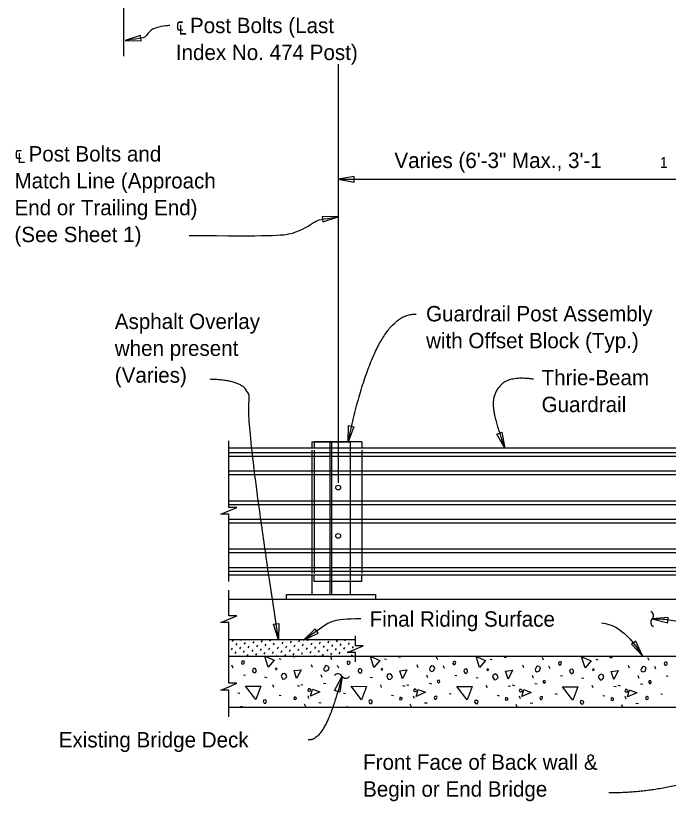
# Model space of a CAD drawing. Extents: x 21652.5 to 21723.2, y 56079.2 to 56117.9.
# Drawn here: x 21654.45 to 21663, y 56092.54 to 56102.84 of the extents above; entities that cross this region are included whole.
import ezdxf

# ---------------------------------------------------------------- set-up
doc = ezdxf.new("R2010")
doc.units = 0
for name, color, linetype in [('Dimension', 7, 'Continuous'), ('ExistSuperStruct', 7, 'Continuous'), ('Miscellaneous', 7, 'Continuous'), ('SteelMisc', 7, 'Continuous'), ('SteelMisc_h', 7, 'Continuous'), ('TextStructures', 7, 'Continuous')]:
    doc.layers.add(name, color=color, linetype=linetype)

msp = doc.modelspace()

# ---------------------------------------------------------------- linework, layer by layer
at = {"layer": 'Dimension'}
for p, q in [((21655.863, 56102.304), (21655.863, 56106.913)), ((21658.671, 56102.202), (21658.671, 56096.715))]:
    msp.add_line(p, q, dxfattribs=at)
for points in [[(21655.88, 56102.511), (21656.091, 56102.505), (21656.081, 56102.575)], [(21658.671, 56100.692), (21658.879, 56100.656), (21658.879, 56100.727)], [(21658.671, 56100.2), (21658.46, 56100.206), (21658.47, 56100.136)], [(21658.803, 56097.253), (21658.808, 56097.465), (21658.877, 56097.451)], [(21660.854, 56097.171), (21660.749, 56097.354), (21660.815, 56097.378)], [(21657.89, 56094.661), (21657.825, 56094.862), (21657.895, 56094.872)], [(21662.783, 56094.932), (21662.988, 56094.882), (21662.993, 56094.952)], [(21658.218, 56094.654), (21658.409, 56094.745), (21658.368, 56094.803)], [(21662.658, 56094.448), (21662.571, 56094.641), (21662.513, 56094.602)], [(21658.722, 56094.184), (21658.691, 56093.975), (21658.624, 56093.996)]]:
    msp.add_lwpolyline(points, close=True, dxfattribs=at)
for points in [[(21658.671, 56100.692), (21672.529, 56100.692)], [(21657.239, 56095.421), (21657.239, 56096.304), (21657.135, 56096.304), (21657.239, 56096.349), (21657.342, 56096.394), (21657.239, 56096.394), (21657.239, 56097.267)], [(21657.239, 56094.414), (21657.239, 56094.884), (21657.135, 56094.884), (21657.239, 56094.929), (21657.342, 56094.974), (21657.239, 56094.974), (21657.239, 56095.308)], [(21658.897, 56094.37), (21658.897, 56094.491), (21658.793, 56094.491), (21658.897, 56094.536), (21659, 56094.581), (21658.897, 56094.581), (21658.897, 56094.711)], [(21657.239, 56093.649), (21657.239, 56093.999), (21657.135, 56093.999), (21657.239, 56094.044), (21657.342, 56094.089), (21657.239, 56094.089), (21657.239, 56094.414)]]:
    msp.add_lwpolyline(points, dxfattribs=at)
for centre, start, end in [((21662.742, 56094.974), 314.1793, 65.9065), ((21662.825, 56094.889), 134.1793, 245.9065), ((21658.669, 56094.154), 30.0081, 141.7354), ((21658.772, 56094.214), 210.0081, 321.7354)]:
    msp.add_arc(centre, 0.0596, start, end, dxfattribs=at)
for points, degree in [([(21656.465, 56102.707), (21656.444, 56102.705), (21656.22, 56102.689), (21656.148, 56102.543), (21656.114, 56102.544), (21655.88, 56102.511)], 3), ([(21656.717, 56099.956), (21657.781, 56099.95), (21658.1, 56099.953), (21658.403, 56100.168), (21658.437, 56100.167), (21658.671, 56100.2)], 3), ([(21658.803, 56097.254), (21659.157, 56098.955), (21659.693, 56098.924)], 2), ([(21657.891, 56094.66), (21657.457, 56097.477), (21657.55, 56098.065), (21656.988, 56098.072)], 2), ([(21661.23, 56098.074), (21660.931, 56098.115), (21660.699, 56097.903), (21660.704, 56097.578), (21660.854, 56097.171)], 2), ([(21658.967, 56094.934), (21658.773, 56094.932), (21658.585, 56094.912), (21658.513, 56094.862), (21658.218, 56094.654)], 3), ([(21662.121, 56094.88), (21662.263, 56094.866), (21662.44, 56094.736), (21662.537, 56094.628), (21662.658, 56094.448)], 3), ([(21665.308, 56093.168), (21664.014, 56094.932), (21662.783, 56094.932)], 2), ([(21658.722, 56094.184), (21658.501, 56093.31), (21658.278, 56093.35)], 2), ([(21663.545, 56092.873), (21662.881, 56092.653), (21662.218, 56092.653)], 2)]:
    msp.add_open_spline(points, degree=degree, dxfattribs=at)
at = {"layer": 'ExistSuperStruct'}
for p, q in [((21657.239, 56095.192), (21663.412, 56095.192)), ((21658.897, 56094.66), (21657.239, 56094.66)), ((21663.412, 56094.442), (21657.239, 56094.442)), ((21657.239, 56093.775), (21663.412, 56093.775))]:
    msp.add_line(p, q, dxfattribs=at)
at = {"layer": 'Miscellaneous'}
for p, q in [((21658.983, 56097.254), (21658.358, 56097.254)), ((21658.358, 56097.254), (21658.358, 56097.171)), ((21658.983, 56097.254), (21658.983, 56097.171)), ((21658.358, 56097.142), (21658.358, 56095.53)), ((21658.983, 56097.142), (21658.983, 56095.53)), ((21658.358, 56095.421), (21658.358, 56095.504)), ((21658.983, 56095.421), (21658.983, 56095.504)), ((21658.983, 56095.421), (21658.358, 56095.421)), ((21657.286, 56094.638), (21657.298, 56094.66)), ((21657.334, 56094.589), (21657.347, 56094.612)), ((21657.383, 56094.54), (21657.396, 56094.563)), ((21657.396, 56094.651), (21657.402, 56094.66)), ((21657.445, 56094.602), (21657.458, 56094.625)), ((21657.494, 56094.553), (21657.507, 56094.576)), ((21657.556, 56094.615), (21657.569, 56094.637)), ((21657.604, 56094.566), (21657.617, 56094.589)), ((21657.666, 56094.628), (21657.679, 56094.65)), ((21657.715, 56094.579), (21657.728, 56094.602)), ((21657.777, 56094.641), (21657.788, 56094.66)), ((21657.826, 56094.592), (21657.839, 56094.615)), ((21657.875, 56094.543), (21657.888, 56094.566)), ((21657.888, 56094.654), (21657.891, 56094.66)), ((21657.936, 56094.605), (21657.949, 56094.628)), ((21657.985, 56094.556), (21657.998, 56094.579)), ((21658.047, 56094.618), (21658.06, 56094.641)), ((21658.096, 56094.569), (21658.109, 56094.592)), ((21658.158, 56094.631), (21658.171, 56094.653)), ((21658.206, 56094.582), (21658.219, 56094.605)), ((21658.268, 56094.644), (21658.278, 56094.66)), ((21658.317, 56094.595), (21658.33, 56094.618)), ((21658.366, 56094.546), (21658.379, 56094.569)), ((21658.379, 56094.657), (21658.381, 56094.66)), ((21658.428, 56094.608), (21658.441, 56094.631)), ((21658.477, 56094.559), (21658.49, 56094.582)), ((21658.538, 56094.621), (21658.551, 56094.644)), ((21658.587, 56094.572), (21658.6, 56094.595)), ((21658.649, 56094.634), (21658.662, 56094.656)), ((21658.698, 56094.585), (21658.711, 56094.608)), ((21658.76, 56094.647), (21658.767, 56094.66)), ((21658.808, 56094.598), (21658.821, 56094.621)), ((21658.857, 56094.549), (21658.87, 56094.572)), ((21658.87, 56094.66), (21658.871, 56094.66)), ((21657.273, 56094.527), (21657.286, 56094.55)), ((21657.321, 56094.479), (21657.334, 56094.501)), ((21657.432, 56094.491), (21657.445, 56094.514)), ((21657.481, 56094.443), (21657.494, 56094.465)), ((21657.543, 56094.504), (21657.556, 56094.527)), ((21657.592, 56094.456), (21657.604, 56094.478)), ((21657.653, 56094.517), (21657.666, 56094.54)), ((21657.702, 56094.469), (21657.715, 56094.491)), ((21657.764, 56094.53), (21657.777, 56094.553)), ((21657.813, 56094.482), (21657.826, 56094.504)), ((21657.923, 56094.495), (21657.936, 56094.517)), ((21657.972, 56094.446), (21657.985, 56094.468)), ((21658.034, 56094.507), (21658.047, 56094.53)), ((21658.083, 56094.459), (21658.096, 56094.481)), ((21658.145, 56094.52), (21658.158, 56094.543)), ((21658.194, 56094.472), (21658.206, 56094.494)), ((21658.255, 56094.533), (21658.268, 56094.556)), ((21658.304, 56094.485), (21658.317, 56094.507)), ((21658.356, 56094.442), (21658.366, 56094.458)), ((21658.415, 56094.498), (21658.428, 56094.52)), ((21658.464, 56094.449), (21658.477, 56094.471)), ((21658.525, 56094.511), (21658.538, 56094.533)), ((21658.574, 56094.462), (21658.587, 56094.484)), ((21658.636, 56094.523), (21658.649, 56094.546)), ((21658.685, 56094.475), (21658.698, 56094.497)), ((21658.747, 56094.536), (21658.76, 56094.559)), ((21658.796, 56094.488), (21658.808, 56094.51)), ((21658.846, 56094.442), (21658.857, 56094.461)), ((21658.906, 56094.501), (21658.906, 56094.501)), ((21657.377, 56094.442), (21657.383, 56094.452)), ((21657.764, 56094.442), (21657.764, 56094.442)), ((21657.867, 56094.442), (21657.875, 56094.455)), ((21657.892, 56094.414), (21657.92, 56094.407)), ((21658.253, 56094.442), (21658.255, 56094.445)), ((21658.59, 56094.398), (21658.576, 56094.434)), ((21658.743, 56094.442), (21658.747, 56094.448)), ((21659.277, 56094.411), (21659.305, 56094.404)), ((21659.975, 56094.395), (21659.961, 56094.43)), ((21660.662, 56094.407), (21660.69, 56094.4)), ((21661.36, 56094.391), (21661.346, 56094.427)), ((21662.046, 56094.404), (21662.075, 56094.397)), ((21662.745, 56094.388), (21662.73, 56094.423)), ((21657.294, 56094.289), (21657.279, 56094.325)), ((21658.334, 56094.298), (21658.32, 56094.333)), ((21658.678, 56094.286), (21658.664, 56094.321)), ((21659.719, 56094.294), (21659.705, 56094.33)), ((21660.063, 56094.282), (21660.049, 56094.318)), ((21661.104, 56094.291), (21661.089, 56094.326)), ((21661.448, 56094.279), (21661.433, 56094.314)), ((21662.488, 56094.287), (21662.474, 56094.322)), ((21662.832, 56094.275), (21662.818, 56094.311)), ((21657.431, 56094.201), (21657.456, 56094.198)), ((21657.707, 56094.173), (21657.737, 56094.167)), ((21658.46, 56094.165), (21658.447, 56094.199)), ((21659.092, 56094.169), (21659.122, 56094.164)), ((21659.844, 56094.162), (21659.832, 56094.195)), ((21660.201, 56094.194), (21660.226, 56094.19)), ((21660.477, 56094.166), (21660.507, 56094.16)), ((21661.229, 56094.158), (21661.217, 56094.192)), ((21661.585, 56094.19), (21661.61, 56094.187)), ((21661.861, 56094.162), (21661.891, 56094.157)), ((21662.614, 56094.154), (21662.601, 56094.188)), ((21662.97, 56094.187), (21662.995, 56094.183)), ((21657.829, 56094.035), (21657.816, 56094.069)), ((21658.135, 56094.061), (21658.163, 56094.054)), ((21658.182, 56094.075), (21658.21, 56094.068)), ((21658.478, 56094.093), (21658.509, 56094.088)), ((21659.24, 56094.035), (21659.228, 56094.069)), ((21659.514, 56094.061), (21659.543, 56094.054)), ((21659.567, 56094.071), (21659.595, 56094.064)), ((21659.863, 56094.09), (21659.893, 56094.084)), ((21660.625, 56094.031), (21660.613, 56094.065)), ((21660.899, 56094.058), (21660.927, 56094.051)), ((21660.951, 56094.068), (21660.98, 56094.061)), ((21661.248, 56094.086), (21661.278, 56094.081)), ((21662.01, 56094.028), (21661.997, 56094.061)), ((21662.284, 56094.054), (21662.312, 56094.047)), ((21662.336, 56094.064), (21662.364, 56094.057)), ((21662.633, 56094.083), (21662.663, 56094.077)), ((21657.357, 56093.964), (21657.384, 56093.959)), ((21658.742, 56093.961), (21658.768, 56093.955)), ((21660.127, 56093.957), (21660.153, 56093.952)), ((21661.511, 56093.954), (21661.538, 56093.948)), ((21662.896, 56093.95), (21662.922, 56093.945)), ((21657.897, 56093.936), (21657.924, 56093.931)), ((21658.288, 56093.892), (21658.276, 56093.926)), ((21659.368, 56093.936), (21659.394, 56093.931)), ((21659.673, 56093.889), (21659.66, 56093.922)), ((21660.752, 56093.932), (21660.779, 56093.927)), ((21661.058, 56093.885), (21661.045, 56093.919)), ((21662.137, 56093.929), (21662.164, 56093.924)), ((21662.442, 56093.882), (21662.43, 56093.915)), ((21658.246, 56093.783), (21658.232, 56093.818)), ((21658.418, 56093.839), (21658.45, 56093.835)), ((21659.63, 56093.779), (21659.616, 56093.815)), ((21659.803, 56093.835), (21659.835, 56093.832)), ((21661.015, 56093.776), (21661.001, 56093.811)), ((21661.188, 56093.832), (21661.22, 56093.828)), ((21662.399, 56093.775), (21662.386, 56093.807)), ((21662.572, 56093.828), (21662.604, 56093.825))]:
    msp.add_line(p, q, dxfattribs=at)
for points in [[(21657.403, 56094.357), (21657.412, 56094.341), (21657.431, 56094.343), (21657.44, 56094.355), (21657.442, 56094.374), (21657.43, 56094.38), (21657.421, 56094.381), (21657.41, 56094.378), (21657.407, 56094.374), (21657.403, 56094.357)], [(21657.755, 56094.302), (21657.71, 56094.442)], [(21657.723, 56094.442), (21657.833, 56094.394), (21657.755, 56094.302)], [(21658.079, 56094.442), (21658.08, 56094.439), (21658.077, 56094.442)], [(21658.08, 56094.439), (21658.101, 56094.439), (21658.103, 56094.442)], [(21658.788, 56094.353), (21658.797, 56094.337), (21658.816, 56094.339), (21658.825, 56094.351), (21658.827, 56094.371), (21658.814, 56094.376), (21658.806, 56094.378), (21658.795, 56094.374), (21658.791, 56094.371), (21658.788, 56094.353)], [(21659.14, 56094.298), (21659.093, 56094.442)], [(21659.1, 56094.442), (21659.217, 56094.39), (21659.14, 56094.298)], [(21659.462, 56094.442), (21659.464, 56094.436), (21659.461, 56094.439)], [(21659.464, 56094.436), (21659.485, 56094.436), (21659.491, 56094.442)], [(21660.173, 56094.35), (21660.181, 56094.334), (21660.201, 56094.335), (21660.21, 56094.348), (21660.211, 56094.367), (21660.199, 56094.373), (21660.19, 56094.374), (21660.18, 56094.371), (21660.176, 56094.367), (21660.173, 56094.35)], [(21660.524, 56094.295), (21660.477, 56094.442), (21660.602, 56094.387), (21660.524, 56094.295)], [(21660.845, 56094.442), (21660.849, 56094.432), (21660.845, 56094.436)], [(21660.849, 56094.432), (21660.87, 56094.432), (21660.88, 56094.442)], [(21661.557, 56094.346), (21661.566, 56094.33), (21661.585, 56094.332), (21661.594, 56094.344), (21661.596, 56094.364), (21661.584, 56094.369), (21661.575, 56094.371), (21661.564, 56094.367), (21661.561, 56094.364), (21661.557, 56094.346)], [(21661.909, 56094.291), (21661.861, 56094.438), (21661.987, 56094.383), (21661.909, 56094.291)], [(21662.229, 56094.442), (21662.228, 56094.441), (21662.234, 56094.429), (21662.23, 56094.432)], [(21662.234, 56094.429), (21662.255, 56094.429), (21662.265, 56094.439), (21662.265, 56094.442)], [(21662.942, 56094.343), (21662.951, 56094.327), (21662.97, 56094.328), (21662.979, 56094.341), (21662.981, 56094.36), (21662.968, 56094.365), (21662.96, 56094.367), (21662.949, 56094.364), (21662.945, 56094.36), (21662.942, 56094.343)], [(21657.548, 56094.258), (21657.559, 56094.236), (21657.576, 56094.226), (21657.591, 56094.236), (21657.598, 56094.247), (21657.598, 56094.268), (21657.582, 56094.284), (21657.562, 56094.282), (21657.553, 56094.274), (21657.548, 56094.258)], [(21657.854, 56094.266), (21657.873, 56094.275), (21657.866, 56094.282), (21657.854, 56094.288), (21657.849, 56094.275), (21657.854, 56094.266)], [(21658.127, 56094.151), (21658.094, 56094.255), (21658.187, 56094.268), (21658.127, 56094.151)], [(21658.488, 56094.261), (21658.511, 56094.248), (21658.541, 56094.261), (21658.553, 56094.298), (21658.536, 56094.315), (21658.513, 56094.321), (21658.502, 56094.314), (21658.49, 56094.294), (21658.481, 56094.278), (21658.488, 56094.261)], [(21658.933, 56094.254), (21658.943, 56094.233), (21658.961, 56094.222), (21658.975, 56094.233), (21658.982, 56094.244), (21658.982, 56094.265), (21658.966, 56094.281), (21658.947, 56094.279), (21658.938, 56094.27), (21658.933, 56094.254)], [(21659.239, 56094.263), (21659.258, 56094.272), (21659.251, 56094.279), (21659.239, 56094.284), (21659.233, 56094.272), (21659.239, 56094.263)], [(21659.512, 56094.147), (21659.478, 56094.252), (21659.572, 56094.264), (21659.512, 56094.147)], [(21659.873, 56094.257), (21659.896, 56094.245), (21659.926, 56094.257), (21659.938, 56094.294), (21659.92, 56094.312), (21659.897, 56094.317), (21659.887, 56094.31), (21659.874, 56094.291), (21659.866, 56094.275), (21659.873, 56094.257)], [(21660.317, 56094.251), (21660.328, 56094.229), (21660.346, 56094.219), (21660.36, 56094.229), (21660.367, 56094.24), (21660.367, 56094.261), (21660.351, 56094.277), (21660.332, 56094.275), (21660.323, 56094.266), (21660.317, 56094.251)], [(21660.623, 56094.259), (21660.643, 56094.268), (21660.636, 56094.275), (21660.623, 56094.281), (21660.618, 56094.268), (21660.623, 56094.259)], [(21660.897, 56094.144), (21660.863, 56094.248), (21660.957, 56094.261), (21660.897, 56094.144)], [(21661.257, 56094.253), (21661.28, 56094.241), (21661.31, 56094.253), (21661.323, 56094.291), (21661.305, 56094.308), (21661.282, 56094.314), (21661.271, 56094.307), (21661.259, 56094.287), (21661.25, 56094.271), (21661.257, 56094.253)], [(21661.702, 56094.247), (21661.713, 56094.226), (21661.73, 56094.215), (21661.745, 56094.226), (21661.752, 56094.236), (21661.752, 56094.258), (21661.736, 56094.274), (21661.716, 56094.272), (21661.707, 56094.263), (21661.702, 56094.247)], [(21662.008, 56094.256), (21662.027, 56094.265), (21662.02, 56094.272), (21662.008, 56094.277), (21662.003, 56094.265), (21662.008, 56094.256)], [(21662.281, 56094.14), (21662.248, 56094.245), (21662.341, 56094.257), (21662.281, 56094.14)], [(21662.642, 56094.25), (21662.665, 56094.238), (21662.695, 56094.25), (21662.707, 56094.287), (21662.69, 56094.305), (21662.667, 56094.31), (21662.656, 56094.303), (21662.644, 56094.284), (21662.635, 56094.268), (21662.642, 56094.25)], [(21657.925, 56094.182), (21657.948, 56094.145), (21657.971, 56094.146), (21657.979, 56094.155), (21657.999, 56094.175), (21657.987, 56094.205), (21657.962, 56094.219), (21657.944, 56094.212), (21657.93, 56094.198), (21657.925, 56094.182)], [(21659.309, 56094.178), (21659.332, 56094.141), (21659.355, 56094.143), (21659.364, 56094.152), (21659.384, 56094.171), (21659.371, 56094.201), (21659.346, 56094.215), (21659.329, 56094.208), (21659.315, 56094.194), (21659.309, 56094.178)], [(21660.694, 56094.175), (21660.717, 56094.137), (21660.74, 56094.139), (21660.749, 56094.148), (21660.768, 56094.167), (21660.756, 56094.198), (21660.731, 56094.212), (21660.713, 56094.205), (21660.699, 56094.19), (21660.694, 56094.175)], [(21662.079, 56094.171), (21662.102, 56094.134), (21662.125, 56094.136), (21662.133, 56094.145), (21662.153, 56094.164), (21662.141, 56094.194), (21662.116, 56094.208), (21662.098, 56094.201), (21662.084, 56094.187), (21662.079, 56094.171)], [(21657.592, 56093.878), (21657.458, 56094.054), (21657.658, 56094.053), (21657.592, 56093.878)], [(21658.977, 56093.874), (21658.843, 56094.051), (21659.042, 56094.049), (21658.977, 56093.874)], [(21659.975, 56094.102), (21659.985, 56094.091), (21659.996, 56094.099), (21660.003, 56094.109), (21659.999, 56094.127), (21659.99, 56094.129), (21659.978, 56094.127), (21659.967, 56094.116), (21659.975, 56094.102)], [(21660.362, 56093.871), (21660.227, 56094.047), (21660.427, 56094.046), (21660.362, 56093.871)], [(21661.359, 56094.099), (21661.37, 56094.088), (21661.38, 56094.095), (21661.387, 56094.106), (21661.384, 56094.123), (21661.375, 56094.125), (21661.363, 56094.123), (21661.352, 56094.113), (21661.359, 56094.099)], [(21662.744, 56094.095), (21662.754, 56094.084), (21662.765, 56094.091), (21662.772, 56094.102), (21662.769, 56094.12), (21662.76, 56094.122), (21662.747, 56094.12), (21662.737, 56094.109), (21662.744, 56094.095)], [(21658.285, 56093.987), (21658.297, 56093.985), (21658.309, 56093.99), (21658.313, 56094.001), (21658.308, 56094.01), (21658.297, 56094.017), (21658.285, 56094.022), (21658.278, 56094.008), (21658.274, 56093.997), (21658.285, 56093.987)], [(21658.307, 56093.922), (21658.335, 56094.014), (21658.429, 56093.977), (21658.307, 56093.922)], [(21659.669, 56093.983), (21659.682, 56093.981), (21659.694, 56093.987), (21659.698, 56093.997), (21659.692, 56094.006), (21659.682, 56094.013), (21659.669, 56094.018), (21659.662, 56094.004), (21659.659, 56093.994), (21659.669, 56093.983)], [(21659.692, 56093.918), (21659.72, 56094.01), (21659.814, 56093.973), (21659.692, 56093.918)], [(21661.054, 56093.979), (21661.066, 56093.978), (21661.079, 56093.983), (21661.082, 56093.994), (21661.077, 56094.002), (21661.066, 56094.01), (21661.054, 56094.015), (21661.047, 56094.001), (21661.043, 56093.99), (21661.054, 56093.979)], [(21661.076, 56093.915), (21661.105, 56094.007), (21661.198, 56093.97), (21661.076, 56093.915)], [(21661.746, 56093.867), (21661.612, 56094.044), (21661.812, 56094.042), (21661.746, 56093.867)], [(21662.439, 56093.976), (21662.451, 56093.974), (21662.463, 56093.979), (21662.467, 56093.99), (21662.462, 56093.999), (21662.451, 56094.006), (21662.439, 56094.011), (21662.432, 56093.997), (21662.428, 56093.987), (21662.439, 56093.976)], [(21662.461, 56093.911), (21662.489, 56094.003), (21662.583, 56093.966), (21662.461, 56093.911)], [(21657.691, 56093.846), (21657.7, 56093.83), (21657.721, 56093.826), (21657.73, 56093.842), (21657.734, 56093.856), (21657.725, 56093.865), (21657.709, 56093.874), (21657.693, 56093.869), (21657.688, 56093.853), (21657.691, 56093.846)], [(21658.091, 56093.881), (21658.11, 56093.876), (21658.123, 56093.885), (21658.124, 56093.897), (21658.121, 56093.901), (21658.107, 56093.908), (21658.094, 56093.906), (21658.093, 56093.893), (21658.091, 56093.881)], [(21659.076, 56093.842), (21659.085, 56093.826), (21659.106, 56093.823), (21659.115, 56093.839), (21659.118, 56093.853), (21659.11, 56093.862), (21659.094, 56093.871), (21659.078, 56093.865), (21659.072, 56093.849), (21659.076, 56093.842)], [(21659.476, 56093.878), (21659.495, 56093.872), (21659.507, 56093.881), (21659.509, 56093.893), (21659.506, 56093.897), (21659.491, 56093.904), (21659.479, 56093.902), (21659.477, 56093.89), (21659.476, 56093.878)], [(21659.939, 56093.883), (21659.946, 56093.883), (21659.96, 56093.89), (21659.966, 56093.906), (21659.964, 56093.915), (21659.95, 56093.922), (21659.932, 56093.911), (21659.929, 56093.901), (21659.932, 56093.89), (21659.939, 56093.883)], [(21660.461, 56093.839), (21660.47, 56093.823), (21660.491, 56093.819), (21660.5, 56093.835), (21660.503, 56093.849), (21660.494, 56093.858), (21660.478, 56093.867), (21660.462, 56093.862), (21660.457, 56093.846), (21660.461, 56093.839)], [(21660.86, 56093.874), (21660.88, 56093.869), (21660.892, 56093.878), (21660.894, 56093.89), (21660.89, 56093.893), (21660.876, 56093.901), (21660.864, 56093.899), (21660.862, 56093.886), (21660.86, 56093.874)], [(21661.324, 56093.879), (21661.331, 56093.879), (21661.345, 56093.886), (21661.35, 56093.902), (21661.349, 56093.911), (21661.334, 56093.918), (21661.317, 56093.908), (21661.313, 56093.897), (21661.317, 56093.886), (21661.324, 56093.879)], [(21661.845, 56093.835), (21661.854, 56093.819), (21661.875, 56093.816), (21661.884, 56093.832), (21661.888, 56093.846), (21661.879, 56093.855), (21661.863, 56093.863), (21661.847, 56093.858), (21661.842, 56093.842), (21661.845, 56093.835)], [(21662.245, 56093.871), (21662.264, 56093.865), (21662.277, 56093.874), (21662.278, 56093.886), (21662.275, 56093.89), (21662.261, 56093.897), (21662.248, 56093.895), (21662.247, 56093.883), (21662.245, 56093.871)], [(21662.709, 56093.876), (21662.716, 56093.876), (21662.73, 56093.883), (21662.735, 56093.899), (21662.733, 56093.908), (21662.719, 56093.915), (21662.701, 56093.904), (21662.698, 56093.893), (21662.701, 56093.883), (21662.709, 56093.876)], [(21657.417, 56093.775), (21657.416, 56093.779), (21657.393, 56093.78), (21657.391, 56093.775)], [(21658.8, 56093.775), (21658.8, 56093.775), (21658.777, 56093.777), (21658.777, 56093.775)]]:
    msp.add_lwpolyline(points, dxfattribs=at)
at = {"layer": 'SteelMisc'}
for p, q in [((21658.327, 56097.254), (21658.827, 56097.254)), ((21658.327, 56097.254), (21658.327, 56097.171)), ((21667.535, 56097.171), (21657.239, 56097.171)), ((21657.239, 56097.115), (21667.535, 56097.115)), ((21657.239, 56097.067), (21667.535, 56097.067)), ((21657.239, 56096.874), (21667.535, 56096.874)), ((21657.239, 56096.826), (21667.535, 56096.826)), ((21657.239, 56096.482), (21667.535, 56096.482)), ((21657.239, 56096.434), (21667.535, 56096.434)), ((21657.239, 56096.241), (21667.535, 56096.241)), ((21657.239, 56096.193), (21667.535, 56096.193)), ((21657.239, 56095.849), (21667.535, 56095.849)), ((21657.239, 56095.801), (21667.535, 56095.801)), ((21657.239, 56095.608), (21667.535, 56095.608)), ((21657.239, 56095.56), (21667.535, 56095.56)), ((21667.535, 56095.504), (21657.239, 56095.504)), ((21658.327, 56095.504), (21658.327, 56095.254)), ((21658.827, 56095.421), (21658.827, 56095.254)), ((21657.994, 56095.254), (21659.16, 56095.254)), ((21657.994, 56095.192), (21657.994, 56095.254)), ((21657.994, 56095.192), (21659.16, 56095.192)), ((21658.327, 56095.254), (21658.827, 56095.254)), ((21659.16, 56095.254), (21659.16, 56095.192))]:
    msp.add_line(p, q, dxfattribs=at)
for centre in [(21658.671, 56096.654), (21658.671, 56096.021)]:
    msp.add_circle(centre, 0.0312, dxfattribs=at)
at = {"layer": 'SteelMisc_h'}
for p, q in [((21658.567, 56095.254), (21658.567, 56097.254)), ((21658.588, 56095.254), (21658.588, 56097.254)), ((21658.827, 56097.254), (21658.827, 56095.441)), ((21658.327, 56097.142), (21658.327, 56095.53))]:
    msp.add_line(p, q, dxfattribs=at)

# ---------------------------------------------------------------- texts
at = {"layer": 'Dimension'}
for s, p in [('℄ Post Bolts (Last', (21656.545, 56102.607)), ('Index No. 474 Post)', (21656.545, 56102.255)), ('℄ Post Bolts and', (21654.431, 56100.925)), ('Match Line (Approach', (21654.431, 56100.573)), ('End or Trailing End)', (21654.431, 56100.221)), ('(See Sheet 1)', (21654.431, 56099.869)), ('Guardrail Post Assembly', (21659.823, 56098.831)), ('Asphalt Overlay', (21655.745, 56098.731)), ('with Offset Block (Typ.)', (21659.823, 56098.479)), ('when present', (21655.745, 56098.379)), ('(Varies)', (21655.745, 56098.027)), ('Thrie-Beam', (21661.336, 56097.994)), ('Guardrail', (21661.336, 56097.642)), ('Front Face of Back wall &', (21658.998, 56092.956)), ('Begin or End Bridge', (21658.998, 56092.604))]:
    msp.add_text(s, height=0.2016, dxfattribs=at).set_placement(p)
at = {"layer": 'TextStructures'}
for s, height, p in [('Varies (6\'-3" Max., 3\'-1', 0.2016, (21659.408, 56100.84)), ('1', 0.141, (21662.885, 56100.842)), ('Final Riding Surface', 0.2016, (21659.083, 56094.831)), ('Existing Bridge Deck', 0.2016, (21655.011, 56093.249))]:
    msp.add_text(s, height=height, dxfattribs=at).set_placement(p)

doc.saveas('drawing.dxf')
